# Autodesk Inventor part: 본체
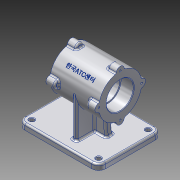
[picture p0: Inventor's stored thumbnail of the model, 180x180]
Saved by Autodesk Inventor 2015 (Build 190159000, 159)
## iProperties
Created: 2015-12
Part Number: 본체
Material: 알루미늄 6061
Document SubType Name: Modeling
Designer: 601-23
Density: 2.7 g/cm^3
Appearance: 알루미늄 - 평지
Mass: 1160.98 g
Surface Area: 818.74 cm^2
Volume: 429.994 cm^3
Author: 601-23
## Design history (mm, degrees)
sketch "스케치1"
  geometry: L1 (0, 0)-(85, 0); L2 (0, 0)-(0, 37); L3 (0, 37)-(85, 37); L4 (85, 37)-(85, 0); L5 (0, 23.5)-(22, 23.5); L6 (22, 23.5)-(22, 21); L7 (22, 21)-(63, 21); L8 (63, 21)-(63, 23.5); L9 (63, 23.5)-(85, 23.5)
  constraints: 18 end point, 6 perpendicular, 4 point on line, 1 horizontal, 1 vertical
  dimensions: "d0" = 85 distance of L1.start L1.end; "d1" = 47 diameter of L5.start L1; "d2" = 74 diameter of L2.end L1; "d3" = 22 distance of L5.start L5.end; "d4" = 22 distance of L8.end L9.end; "d5" = 42 diameter of L7.end L1
revolve "회전1" sketch "스케치1" stored, may be unused: angle "d6" = 90 deg
sketch "스케치2"
  geometry: L1 (0, -37)-(0, 37) reference; L2 (85, -37)-(85, 37) reference; L3 (-37.5, -70)-(102.5, -70); L4 (102.5, -70)-(102.5, -80); L5 (102.5, -80)-(-37.5, -80); L6 (-37.5, -80)-(-37.5, -70); L7 (0, -37)-(85, -37) reference; L8 (42.5, -37)-(42.5, -70); L9 (85, -23.5)-(85, 23.5) reference; L10 (63, -21)-(63, 21) reference; L11 (22, -21)-(22, 21) reference; 1 further point
  constraints: 10 end point, 2 parallel, 2 perpendicular, 1 horizontal, 1 midpoint, 1 point on line
  dimensions: "d7" = 140 distance of L4.end L5.end; "d8" = 10 distance of L3.end L4.end; "d9" = 80 distance between parallel lines of L8 L6; "d10" = 80 distance from line of L5 point (0, 0)
extrude "돌출1" join sketch "스케치2" stored distance "d11" = 110; taper "d12" = 0 deg
sketch "스케치3"
  geometry: L1 (140, 0)-(140, 110) reference; L2 (0, 0)-(140, 0) reference; L3 (0, 0)-(0, 110) reference; L4 (140, 110)-(0, 110) reference; L5 (55, 61)-(105, 61); L6 (105, 61)-(105, 49); L7 (105, 49)-(55, 49); L8 (55, 49)-(55, 61); L9 (76, 92)-(84, 92); L10 (84, 92)-(84, 18); L11 (84, 18)-(76, 18); L12 (76, 18)-(76, 92); 6 further points
  constraints: 16 end point, 5 midpoint, 4 parallel, 2 horizontal, 2 horizontal alignment, 2 perpendicular, 1 vertical alignment
  dimensions: "d13" = 12 distance of L7.end L5.start; "d14" = 8 distance of L9.start L9.end; "d15" = 74 distance of L9.end L10.end; "d16" = 50 distance of L6.end L7.end; "d17" = 80 distance from line of L3 point (80, 92)
  node "투영된 루프3"
extrude "돌출2" join sketch "스케치3" stored distance "d18" = 110; taper "d19" = 0 deg
extrude "돌출3" join sketch "스케치3" stored distance "d20" = 110; taper "d21" = 0 deg
sketch "스케치4"
  geometry: C1 r 23.5 at (0, 0) reference; C2 r 7 at (0, 37); 2 further points
  constraints: 2 vertical alignment, 1 centre point, 1 other
  dimensions: "d22" = 14 diameter of C2
extrude "돌출4" join sketch "스케치4" distance "d23" = 15; taper "d24" = 0 deg
sketch "스케치5"
  geometry: C1 r 23.5 at (0, -37) reference; A1 r 37 centre (0, -37) between (-6.969, -0.662) and (6.969, -0.662) reference; A2 r 7 centre (0, 0) between (6.969, -0.662) and (-6.969, -0.662) reference; 3 further points
  constraints: 2 coincident, 2 vertical alignment, 2 other
hole "구멍1" sketch "스케치5" at (0, 0) diameter "d26" = 3.242; stored, may be unused: countersink angle "d30" = 90 deg, drill point angle "d32" = 118 deg; dims "d27" = 9, "d28" = 4, "d29" = 2, "d31" = 11
fillet "모깎기2" dims "d36" = 12
sketch "스케치6"
  geometry: L1 (0, -110)-(116, -110) reference; L2 (-12, -98)-(-12, -12) reference; L3 (116, 0)-(0, 0) reference; L4 (128, -98)-(128, -12) reference; A1 r 12 centre (116, -98) between (116, -110) and (128, -98) reference; A2 r 12 centre (0, -98) between (-12, -98) and (0, -110) reference; A3 r 12 centre (0, -12) between (0, 0) and (-12, -12) reference; A4 r 12 centre (116, -12) between (128, -12) and (116, 0) reference; 2 further points
  dimensions: "d37" = 12 distance from line of L4 point (116, -98); "d38" = 12 distance from line of point (116, -98) L1
hole "구멍2" sketch "스케치6" at (116, -98) diameter "d39" = 8; stored, may be unused: countersink angle "d43" = 90 deg, drill point angle "d45" = 0 deg; dims "d40" = 8, "d41" = 4, "d42" = 2, "d44" = 11
chamfer "모따기1" distance "d46" = 1; stored, may be unused: second distance "d47" = 2, angle "d48" = 45 deg
fillet "모깎기3" dims "d55" = 0.3
chamfer "모따기2" distance "d56" = 1; stored, may be unused: second distance "d57" = 2, angle "d58" = 45 deg
fillet "모깎기4" dims "d59" = 3
feature "면 기울기1" dims angle "d60" = 7 deg
feature "면 기울기2" dims angle "d61" = 7 deg
feature "면 기울기3" dims angle "d62" = 7 deg
fillet "모깎기5" dims "d63" = 3
fillet "모깎기6" dims "d64" = 3
fillet "모깎기7" dims "d65" = 3
fillet "모깎기8" dims "d66" = 3
fillet "모깎기9" dims "d67" = 3
node "작업 평면2"
node "작업 평면4"
  node "작업 평면3"
sketch "스케치7"
  geometry: L1 (42.5, -37)-(-42.5, -37) reference; L2 (42.5, 18.921)-(42.5, -18.921) reference; L3 (42.5, -37)-(-42.5, -37) reference; 3 further points
  constraints: 1 horizontal alignment, 1 midpoint, 1 other
  dimensions: "d72" = 42.5 distance from line of L2 point (0, 0)
feature "엠보싱1" sketch "스케치7" dims "d0" = 85, "d1" = 47, "d2" = 74, "d3" = 22, "d4" = 22, "d5" = 42, "d8" = 10, "d73" = 0.5, "d74" = 0
node "솔리드1"
pattern_linear "직사각형 패턴1" dims "d51" = 116, "d54" = 86
pattern_circular "원형 패턴2" dims "d69" = 360 deg
mirror "대칭2"
node "투영된 루프1"
node "투영된 루프2"
node "투영된 루프4"
node "투영된 루프5"
node "투영된 루프6"
node "작업축1"
other parameters: "d71" = -45 deg
